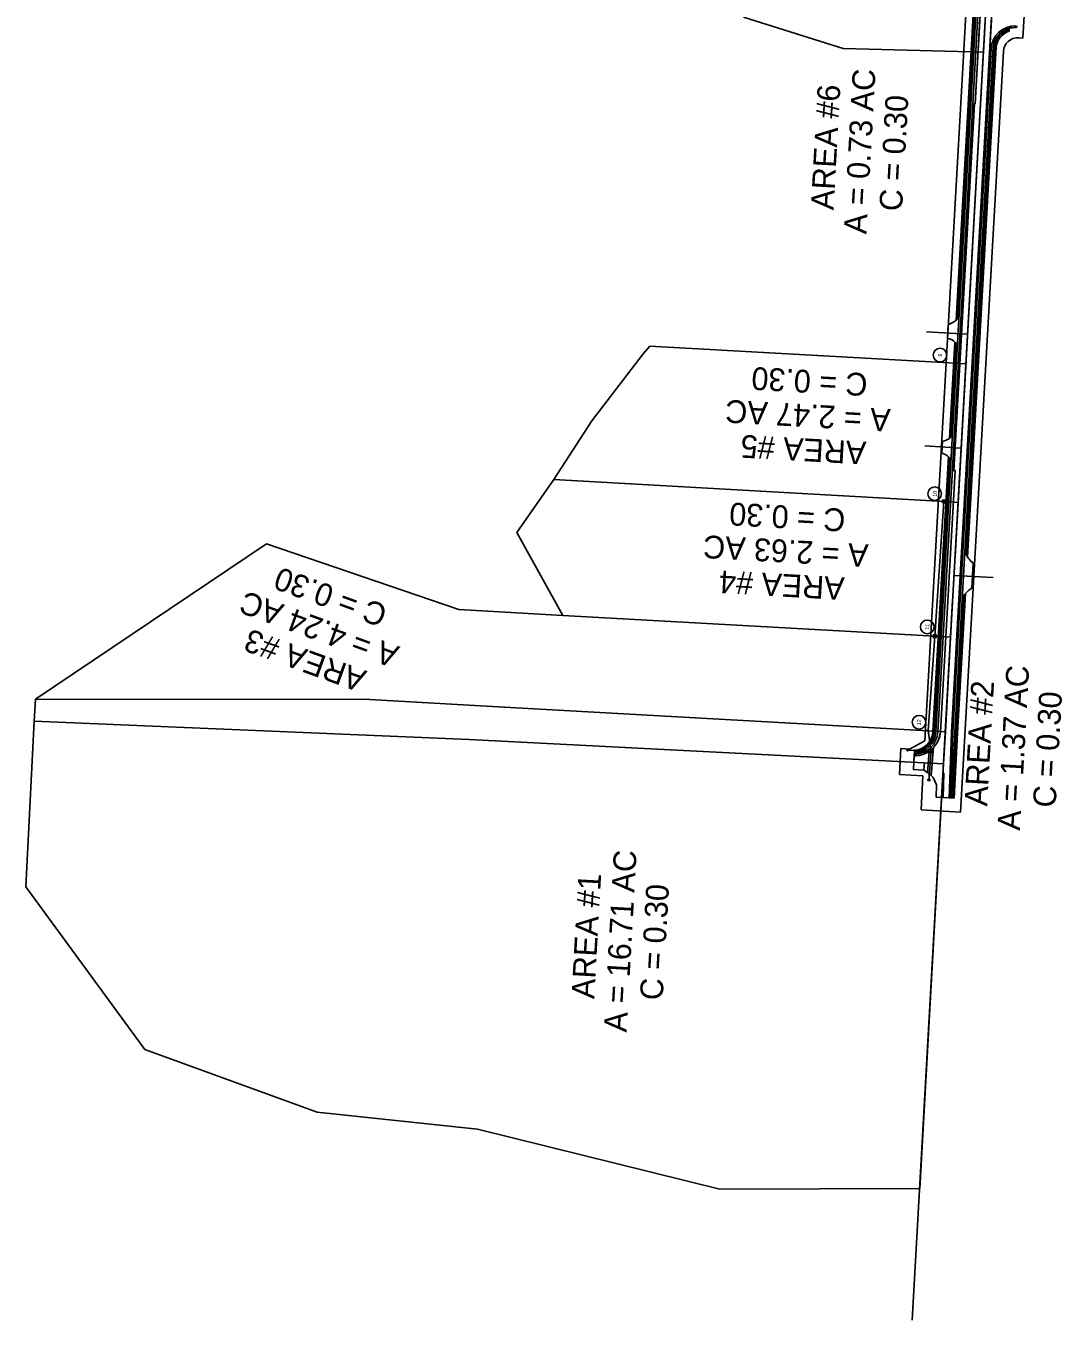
# Model space of a CAD drawing. Extents: x 1972588 to 1974207, y 734965 to 738282.
# Drawn here: x 1972588 to 1974103, y 734965 to 736857 of the extents above; entities that cross this region are included whole.
import ezdxf

# ---------------------------------------------------------------- set-up
doc = ezdxf.new("R2010")
doc.units = 0
for name, color, linetype in [('_CIVIL_CONSTRUCTION', 7, 'Continuous'), ('BR_P_Gen_Ground_Slope', 7, 'Continuous'), ('BR_P_Gen_Hatch', 7, 'Continuous'), ('BR_X_Beam Seat', 7, 'Continuous'), ('BR_X_Pier', 7, 'Continuous'), ('DR_P_GenericNode', 7, 'Continuous'), ('DR_P_Headwall', 7, 'Continuous'), ('DR_P_Storm_Sewer', 7, 'Continuous'), ('DR_X_Cells', 7, 'Continuous'), ('DR_X_Storm_Sewer', 7, 'Continuous'), ('DT_X_Contour_Major', 7, 'Continuous'), ('GE_P_Alignment', 7, 'Continuous'), ('GE_X_Alignment_1000_Cardinal_Points', 7, 'Continuous'), ('GK_Drainage_Nodes', 7, 'Continuous'), ('PF_P_Grade_Line', 7, 'Continuous'), ('RS_Raster1', 7, 'Continuous'), ('SC_ProfileRun2', 7, 'Continuous'), ('SC_ProfileRun4', 7, 'Continuous'), ('SC_Scratch1', 7, 'Continuous')]:
    doc.layers.add(name, color=color, linetype=linetype)

msp = doc.modelspace()

# ---------------------------------------------------------------- linework, layer by layer
at = {"layer": '_CIVIL_CONSTRUCTION'}
for p, q in [((1973937, 736420), (1973942.6, 736422.6)), ((1973935.9, 736400), (1973937, 736420)), ((1973936, 736399.9), (1973935.9, 736400)), ((1973927.5, 736232.2), (1973928.4, 736249.8)), ((1973928.9, 736249.8), (1973928.4, 736249.8)), ((1973927.5, 736232.2), (1973928.9, 736231.8)), ((1973969.6, 736074.9), (1973973.5, 736071.6)), ((1973971.5, 736034.5), (1973973.5, 736071.6)), ((1973968.2, 736032.6), (1973970.6, 736034.4)), ((1973970.6, 736034.4), (1973971.5, 736034.5))]:
    msp.add_line(p, q, dxfattribs=at)
for centre, radius, start, end in [((1973931.4, 736445), 25, 294.7103, 328.4316), ((1973932.8, 736380.2), 20, 28.5776, 80.6006), ((1973926.6, 736269.7), 20, 276.6259, 325.0009), ((1973923.3, 736212.6), 20, 28.5776, 73.8061), ((1973994.2, 736100), 35, 200.6847, 230.3381), ((1973988.8, 736004.3), 35, 126.025, 152.8937)]:
    msp.add_arc(centre, radius, start, end, dxfattribs=at)
at = {"layer": 'BR_P_Gen_Ground_Slope'}
for points in [[(1973876.9, 735797.6), (1973877.9, 735797.6), (1973877.9, 735797.1), (1973876.9, 735797.1), (1973877, 735799.1), (1973878, 735799.1), (1973878, 735798.6), (1973877, 735798.6)], [(1973909.3, 735753.7), (1973909.4, 735755.2), (1973910.2, 735755.2), (1973910.1, 735753.7), (1973907.1, 735753.9), (1973907.2, 735755.4), (1973907.9, 735755.3), (1973907.8, 735753.8)]]:
    msp.add_lwpolyline(points, dxfattribs=at)
at = {"layer": 'BR_P_Gen_Hatch'}
for p, q in [((1973915.4, 735801.8), (1973912.1, 735760.8)), ((1973909, 735796.3), (1973906.5, 735765.3)), ((1973910.2, 735762.8), (1973906.5, 735765.3)), ((1973912.1, 735760.8), (1973910.2, 735762.8))]:
    msp.add_line(p, q, dxfattribs=at)
at = {"layer": 'BR_X_Beam Seat'}
for p, q in [((1973902.9, 735811.8), (1973981.5, 737212.7)), ((1974049.4, 736896.9), (1974046.1, 736839)), ((1974039.7, 736839.4), (1974046.1, 736839)), ((1973955.1, 735707.5), (1974017.5, 736819.6)), ((1973867.7, 735800.3), (1973865.6, 735762.4)), ((1973867.7, 735800.3), (1973880.4, 735799.7)), ((1973880.4, 735799.7), (1973902.9, 735811.8)), ((1973865.6, 735762.4), (1973900, 735760.6)), ((1973897.2, 735710.7), (1973900, 735760.6)), ((1973955.1, 735707.5), (1973897.2, 735710.7))]:
    msp.add_line(p, q, dxfattribs=at)
msp.add_arc((1974038.5, 736818.4), 21, 86.7317, 176.7892, dxfattribs=at)
at = {"layer": 'BR_X_Pier'}
for p, q in [((1973993.6, 736911.9), (1973988.4, 736818.5)), ((1973637.6, 736869.7), (1973783.2, 736823.8)), ((1973988.4, 736818.5), (1973783.2, 736823.8)), ((1973490.9, 736377.2), (1973500.7, 736388.6)), ((1973938.4, 736364.1), (1973500.7, 736388.6)), ((1973415.8, 736279.6), (1973490.9, 736377.2)), ((1973938.4, 736364.1), (1973962.8, 736362.7)), ((1973951.5, 736160.3), (1973962.8, 736362.7)), ((1973360.4, 736193.5), (1973415.8, 736279.6)), ((1973306.3, 736116.4), (1973360.4, 736193.5)), ((1973930.7, 736161.5), (1973360.4, 736193.5)), ((1973930.7, 736161.5), (1973951.5, 736160.3)), ((1973940.4, 735963.3), (1973951.5, 736160.3)), ((1973306.3, 736116.4), (1973373.6, 735995.1)), ((1972602.5, 735872.8), (1972940.3, 736099.7)), ((1972940.3, 736099.7), (1973221.3, 736003.7)), ((1973373.6, 735995.1), (1973221.3, 736003.7)), ((1973917.2, 735964.7), (1973373.6, 735995.1)), ((1973917.2, 735964.7), (1973940.4, 735963.3)), ((1973932.7, 735824.9), (1973940.4, 735963.3)), ((1972600.7, 735840.6), (1972602.5, 735872.8)), ((1972602.5, 735872.8), (1973091.1, 735872.1)), ((1973253.3, 735863), (1973091.1, 735872.1)), ((1973907.7, 735826.3), (1973253.3, 735863)), ((1972600.7, 735840.6), (1972588.4, 735598.5)), ((1973236.5, 735813.6), (1972600.7, 735840.6)), ((1973907.7, 735826.3), (1973932.7, 735824.9)), ((1973930, 735778.1), (1973932.7, 735824.9)), ((1973930, 735778.1), (1973236.5, 735813.6)), ((1973236.5, 735813.6), (1973236.5, 735813.6)), ((1973930, 735778.1), (1973895.2, 735157.2)), ((1972588.4, 735598.5), (1972762.2, 735360.4)), ((1972762.2, 735360.4), (1973014.3, 735268.9)), ((1973014.3, 735268.9), (1973248.9, 735243.9)), ((1973602.8, 735156.5), (1973248.9, 735243.9)), ((1973895.2, 735157.2), (1973602.8, 735156.5))]:
    msp.add_line(p, q, dxfattribs=at)
for centre in [(1973924.9, 736375.6), (1973917.1, 736173), (1973906.2, 735978.3), (1973894.2, 735838.9)]:
    msp.add_circle(centre, 10, dxfattribs=at)
at = {"layer": 'DR_P_GenericNode'}
for points in [[(1973928.4, 736159.5), (1973928.7, 736163.8), (1973933, 736163.5), (1973932.8, 736159.2)], [(1973929.1, 736160.1), (1973929.3, 736163.1), (1973932.3, 736162.9), (1973932.1, 736159.9)], [(1973929.5, 736160.4), (1973929.6, 736162.7), (1973931.9, 736162.6), (1973931.8, 736160.3)], [(1973914.9, 735962.6), (1973915.2, 735966.9), (1973919.5, 735966.7), (1973919.2, 735962.4)], [(1973915.6, 735963.2), (1973915.8, 735966.2), (1973918.8, 735966.1), (1973918.6, 735963.1)], [(1973916, 735963.6), (1973916.1, 735965.9), (1973918.4, 735965.7), (1973918.3, 735963.4)]]:
    msp.add_lwpolyline(points, close=True, dxfattribs=at)
for centre, radius in [((1973912, 735796.6), 2.42), ((1973912, 735796.6), 2), ((1973912.7, 735796.5), 1)]:
    msp.add_circle(centre, radius, dxfattribs=at)
at = {"layer": 'DR_P_Headwall'}
for p, q in [((1973905.2, 736409.5), (1973965.3, 736406.1)), ((1973902.7, 736242.7), (1973955.9, 736239.7)), ((1974002.4, 736050.4), (1973945.5, 736053.6))]:
    msp.add_line(p, q, dxfattribs=at)
at = {"layer": 'DR_P_Storm_Sewer'}
for p, q in [((1973918.6, 735825.1), (1973996.4, 737211.9)), ((1973956.5, 736000.9), (1974002.8, 736825.8)), ((1973946.6, 735823.5), (1973956.5, 736000.9)), ((1973941.8, 735728.3), (1973946.6, 735823.5)), ((1973887.4, 735793.9), (1973887.3, 735791.9))]:
    msp.add_line(p, q, dxfattribs=at)
for centre, radius, start, end in [((1974034.9, 736822.2), 32.3, 105.7454, 173.6261), ((1973886.2, 735826.4), 32.5, 272.1064, 357.7326)]:
    msp.add_arc(centre, radius, start, end, dxfattribs=at)
at = {"layer": 'DR_X_Cells'}
for p, q in [((1973950.5, 736428.9), (1973994.4, 737212)), ((1974026, 736851.1), (1974026.2, 736853.3)), ((1973963.2, 736083.6), (1974004.8, 736825.6)), ((1973940.8, 736255.6), (1973948.5, 736392.6)), ((1973916.6, 735825.2), (1973939.1, 736224.9)), ((1973948.6, 735823.4), (1973959.8, 736024)), ((1973943.8, 735728.2), (1973948.6, 735823.4)), ((1973887.5, 735795.9), (1973887.4, 735793.9)), ((1973941.8, 735728.3), (1973943.8, 735728.2))]:
    msp.add_line(p, q, dxfattribs=at)
for centre, radius, start, end in [((1974034.9, 736822.2), 30.3, 107.054, 173.6261), ((1973886.1, 735826.4), 30.5, 272.5004, 357.7242)]:
    msp.add_arc(centre, radius, start, end, dxfattribs=at)
at = {"layer": 'DR_X_Storm_Sewer'}
for p, q in [((1973989.9, 736846.3), (1973947, 736081.2)), ((1973943.4, 736017.1), (1973932.6, 735824.3)), ((1973932.6, 735824.3), (1973932.1, 735808.6)), ((1973930.6, 735764.3), (1973929.3, 735729))]:
    msp.add_line(p, q, dxfattribs=at)
at = {"layer": 'DT_X_Contour_Major'}
for p, q in [((1973917.2, 735964.7), (1973930.7, 736161.5)), ((1973907.7, 735826.3), (1973917.2, 735964.7)), ((1973907.7, 735826.3), (1973912, 735796.6)), ((1973912, 735796.6), (1973877, 735798.1)), ((1973912, 735796.6), (1973908.6, 735753.8))]:
    msp.add_line(p, q, dxfattribs=at)
at = {"layer": 'GE_P_Alignment'}
for p, q in [((1973997.7, 736824), (1974019.4, 737210.7)), ((1973976.1, 736742.9), (1973993, 737044.3)), ((1973951.6, 736001.2), (1973997.7, 736824)), ((1973945.1, 736206.9), (1973975.1, 736743)), ((1973976.1, 736742.9), (1973975.1, 736743)), ((1973925.6, 735824.7), (1973947.1, 736206.8)), ((1973947.1, 736206.8), (1973945.1, 736206.9)), ((1973941.6, 735823.8), (1973951.6, 736001.2)), ((1973938.2, 735728.5), (1973941.6, 735823.8)), ((1973887.1, 735789.9), (1973887.3, 735791.9)), ((1973938.2, 735728.5), (1973940.2, 735728.4))]:
    msp.add_line(p, q, dxfattribs=at)
msp.add_arc((1973887.7, 735827.9), 38, 269.0839, 355.1753, dxfattribs=at)
at = {"layer": 'GE_X_Alignment_1000_Cardinal_Points'}
for p, q in [((1973928.6, 736161.6), (1973928.6, 736161.6)), ((1973929.2, 736161.6), (1973929.2, 736161.6)), ((1973930.6, 736160), (1973930.6, 736160)), ((1973930.7, 736161.5), (1973930.7, 736161.5)), ((1973930.7, 736161.5), (1973930.7, 736161.5)), ((1973930.7, 736161.5), (1973930.7, 736161.5)), ((1973930.8, 736163), (1973930.8, 736163)), ((1973932.2, 736161.4), (1973932.2, 736161.4)), ((1973932.9, 736161.4), (1973932.9, 736161.4)), ((1973915, 735964.8), (1973915, 735964.8)), ((1973915.7, 735964.7), (1973915.7, 735964.7)), ((1973917.1, 735963.2), (1973917.1, 735963.2)), ((1973917.2, 735964.7), (1973917.2, 735964.7)), ((1973917.2, 735964.7), (1973917.2, 735964.7)), ((1973917.2, 735964.7), (1973917.2, 735964.7)), ((1973917.3, 735966.1), (1973917.3, 735966.1)), ((1973918.7, 735964.6), (1973918.7, 735964.6)), ((1973919.4, 735964.5), (1973919.4, 735964.5)), ((1973877, 735798.1), (1973877, 735798.1)), ((1973877, 735798.1), (1973877, 735798.1)), ((1973877, 735798.1), (1973877, 735798.1)), ((1973877, 735798.1), (1973877, 735798.1)), ((1973877, 735798.1), (1973877, 735798.1)), ((1973878, 735798.1), (1973878, 735798.1)), ((1973910, 735796.7), (1973910, 735796.7)), ((1973912, 735796.6), (1973912, 735796.6)), ((1973912, 735796.6), (1973912, 735796.6)), ((1973912.7, 735796.5), (1973912.7, 735796.5)), ((1973914, 735796.4), (1973914, 735796.4)), ((1973908.6, 735753.8), (1973908.6, 735753.8)), ((1973908.6, 735753.8), (1973908.6, 735753.8)), ((1973908.6, 735753.8), (1973908.6, 735753.8)), ((1973908.6, 735753.8), (1973908.6, 735753.8)), ((1973908.6, 735753.8), (1973908.6, 735753.8)), ((1973908.7, 735755.3), (1973908.7, 735755.3))]:
    msp.add_line(p, q, dxfattribs=at)
msp.add_circle((1973912, 735796.6), 2, dxfattribs=at)
at = {"layer": 'GK_Drainage_Nodes'}
for p, q in [((1974026.2, 736853.3), (1974026.3, 736855.9)), ((1974035.8, 736854.4), (1974036.9, 736854.3)), ((1974037.1, 736856.8), (1974036.9, 736854.3))]:
    msp.add_line(p, q, dxfattribs=at)
msp.add_arc((1974034.7, 736821.9), 32.5, 87.9533, 105.1589, dxfattribs=at)
at = {"layer": 'PF_P_Grade_Line'}
for points in [[(1973925.6, 735824.7), (1973947.1, 736206.8), (1973945.1, 736206.9), (1973975.1, 736743), (1973976.1, 736742.9), (1973993, 737044.3), (1973992, 737044.4), (1974001.4, 737211.6), (1974015.3, 737479.1), (1974038.5, 737880.6), (1974055.1, 737874.3), (1974032.3, 737478.2), (1974033.3, 737478.1), (1974019.4, 737210.7), (1973941.6, 735823.8), (1973938.2, 735728.5), (1973919.2, 735729.5), (1973919.9, 735747.5), (1973914.9, 735757.9), (1973912.1, 735760.8), (1973915.4, 735801.8)], [(1973915.4, 735801.8), (1973912.1, 735760.8), (1973910.2, 735762.8), (1973906.5, 735765.3), (1973909, 735796.3)], [(1973909, 735796.3), (1973906.5, 735765.3), (1973901.5, 735768.6), (1973886, 735769.9), (1973887.1, 735789.9)]]:
    msp.add_lwpolyline(points, dxfattribs=at)
for start, end in [(316.7159, 355.1753), (303.9259, 316.7159), (269.0839, 303.9259)]:
    msp.add_arc((1973887.7, 735827.9), 38, start, end, dxfattribs=at)
at = {"layer": 'RS_Raster1'}
msp.add_line((1973884.4, 734964.9), (1974010.4, 737211.2), dxfattribs=at)
at = {"layer": 'SC_ProfileRun2'}
msp.add_line((1973902.2, 735780.2), (1973901.5, 735768.6), dxfattribs=at)
at = {"layer": 'SC_ProfileRun4'}
for p, q in [((1973948.4, 736426.7), (1973992.4, 737212.2)), ((1974025.9, 736849), (1974026, 736851.1)), ((1973965, 736080.6), (1974006.8, 736825.5)), ((1973938.7, 736253.8), (1973946.6, 736394.7)), ((1973914.6, 735825.3), (1973937.2, 736227)), ((1973950.6, 735823.3), (1973962, 736026.9)), ((1973945.8, 735728), (1973950.6, 735823.3)), ((1973887.6, 735797.9), (1973887.5, 735795.9)), ((1973943.8, 735728.2), (1973945.8, 735728))]:
    msp.add_line(p, q, dxfattribs=at)
for centre, radius, start, end in [((1974034.9, 736822.2), 28.3, 108.5611, 173.6261), ((1973886.1, 735826.4), 28.5, 272.8819, 357.7242)]:
    msp.add_arc(centre, radius, start, end, dxfattribs=at)
at = {"layer": 'SC_Scratch1'}
for p, q in [((1973921.6, 735824.9), (1973999.4, 737211.8)), ((1973953.6, 736001.1), (1973999.7, 736823.9)), ((1973943.6, 735823.7), (1973953.6, 736001.1)), ((1973940.2, 735728.4), (1973943.6, 735823.7)), ((1973887.3, 735791.9), (1973886, 735769.9)), ((1973886, 735769.9), (1973901.5, 735768.6)), ((1973901.5, 735768.6), (1973910.2, 735762.8)), ((1973910.2, 735762.8), (1973914.9, 735757.9)), ((1973914.9, 735757.9), (1973919.9, 735747.5)), ((1973919.9, 735747.5), (1973919.2, 735729.5)), ((1973940.2, 735728.4), (1973919.2, 735729.5)), ((1973940.2, 735728.4), (1973941.8, 735728.3))]:
    msp.add_line(p, q, dxfattribs=at)
for centre, start, end in [((1974034.7, 736821.9), 87.9533, 176.7892), ((1973886.7, 735826.9), 270.9216, 356.7892)]:
    msp.add_arc(centre, 35, start, end, dxfattribs=at)

# ---------------------------------------------------------------- texts
at = {"layer": 'BR_X_Pier'}
for s, height, rotation, p in [('A = 0.73 AC', 33.33, 86.7892, (1973817.3, 736551.9)), ('AREA #6', 33.33, 86.7892, (1973769.2, 736587.1)), ('C = 0.30', 33.33, 86.7892, (1973869.3, 736585.3)), ('9', 5.6, 86.7892, (1973927.5, 736373.2)), ('C = 0.30', 33.33, 176.7892, (1973819.8, 736348.8)), ('A = 2.47 AC', 33.33, 176.7892, (1973853.3, 736296.8)), ('AREA #5', 33.33, 176.7892, (1973817.6, 736248.8)), ('10', 5.6, 86.7892, (1973919.7, 736168.4)), ('C = 0.30', 33.33, 176.7892, (1973787.4, 736150.7)), ('A = 2.63 AC', 33.33, 176.7892, (1973820.9, 736098.8)), ('C = 0.30', 33.33, 160.0484, (1973119.2, 736008.5)), ('AREA #4', 33.33, 176.7892, (1973786, 736050.7)), ('A = 4.24 AC', 33.33, 160.0484, (1973136.3, 735949.1)), ('AREA #3', 33.33, 160.0484, (1973088.2, 735913.4)), ('11', 5.6, 86.7892, (1973908.8, 735974.1)), ('A = 1.37 AC', 33.33, 86.7892, (1974041.9, 735680)), ('AREA #2', 33.33, 86.7892, (1973993.8, 735715.6)), ('C = 0.30', 33.33, 86.7892, (1974093.9, 735713.5)), ('12', 5.6, 86.7892, (1973896.8, 735834.4)), ('A = 16.71 AC', 33.33, 86.7892, (1973466.6, 735385.2)), ('AREA #1', 33.33, 86.7892, (1973419.3, 735434)), ('C = 0.30', 33.33, 86.7892, (1973519.3, 735431.9))]:
    msp.add_text(s, height=height, rotation=rotation, dxfattribs=at).set_placement(p)

doc.saveas('drawing.dxf')
